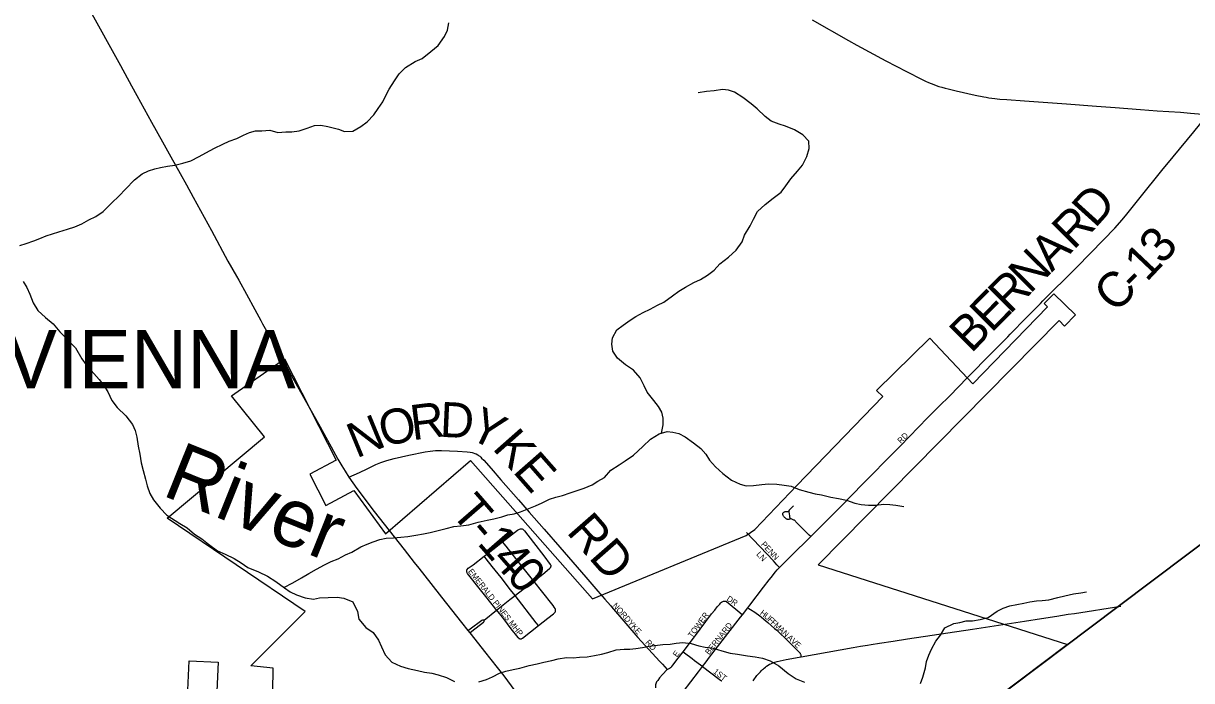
# Model space of a CAD drawing. Extents: x 1442749 to 1756758, y 235267 to 677782.
# Drawn here: x 1626273 to 1636274, y 485248 to 490876 of the extents above; entities that cross this region are included whole.
import ezdxf

# ---------------------------------------------------------------- set-up
doc = ezdxf.new("R2010")
doc.units = 0
for name, color, linetype in [('GM_X_Adjacent_County', 7, 'Continuous'), ('GM_X_City_Street', 7, 'Continuous'), ('GM_X_City_Street_Text', 7, 'Continuous'), ('GM_X_Corporation', 7, 'Continuous'), ('GM_X_Corporation_Text', 7, 'Continuous'), ('GM_X_County', 7, 'Continuous'), ('GM_X_County_Road', 7, 'Continuous'), ('GM_X_County_Road_Text', 7, 'Continuous'), ('GM_X_Major_River', 7, 'Continuous'), ('GM_X_Major_River_Text', 7, 'Continuous'), ('GM_X_Minor_River', 7, 'Continuous'), ('GM_X_State_Route', 7, 'Continuous'), ('GM_X_Township', 7, 'Continuous'), ('GM_X_Township_Road', 7, 'Continuous'), ('GM_X_Township_Road_Text', 7, 'Continuous')]:
    doc.layers.add(name, color=color, linetype=linetype)

msp = doc.modelspace()

# ---------------------------------------------------------------- linework, layer by layer
at = {"layer": 'GM_X_Adjacent_County'}
msp.add_lwpolyline([(1614700, 470050), (1618604, 472952), (1620523, 474378), (1621966, 475451), (1621997, 475474), (1628919, 480818), (1628958, 480847), (1631413, 482696), (1633248, 484078), (1633505, 484272), (1633819, 484508), (1635644, 485883), (1638042, 487688), (1640676, 489672), (1647133, 494533), (1648023, 495203), (1648788, 495779), (1655741, 500852)], dxfattribs=at)
at = {"layer": 'GM_X_City_Street'}
for points in [[(1633013, 486483), (1633279, 486749), (1633458, 486933), (1633737, 487213), (1633783, 487260), (1634014, 487497), (1634109, 487596), (1634203, 487688), (1634353, 487840)], [(1632840, 486636), (1632839, 486635), (1632837, 486634), (1632837, 486633), (1632836, 486632), (1632834, 486631), (1632833, 486631), (1632831, 486630), (1632826, 486629), (1632823, 486628), (1632819, 486628), (1632815, 486629), (1632812, 486630), (1632807, 486632), (1632803, 486634), (1632794, 486642), (1632790, 486646), (1632785, 486651), (1632782, 486654), (1632781, 486656), (1632778, 486661), (1632776, 486664), (1632775, 486668), (1632774, 486671), (1632774, 486676), (1632774, 486679), (1632775, 486682), (1632777, 486684), (1632778, 486686), (1632780, 486688), (1632780, 486689), (1632784, 486691), (1632786, 486692), (1632790, 486694), (1632794, 486695), (1632805, 486695), (1632815, 486695), (1632822, 486695), (1632828, 486694)], [(1632828, 486694), (1632828, 486697), (1632828, 486699), (1632828, 486700), (1632828, 486701), (1632828, 486702), (1632828, 486703), (1632829, 486704), (1632829, 486704), (1632830, 486706), (1632830, 486707), (1632832, 486710), (1632833, 486711), (1632834, 486713), (1632835, 486714), (1632839, 486718), (1632867, 486745)], [(1632840, 486636), (1632839, 486638), (1632838, 486640), (1632837, 486641), (1632836, 486643), (1632836, 486644), (1632835, 486646), (1632834, 486650), (1632834, 486653), (1632833, 486656), (1632833, 486660), (1632828, 486694)], [(1633013, 486483), (1633001, 486495), (1632930, 486566), (1632886, 486609), (1632883, 486613), (1632879, 486616), (1632877, 486618), (1632873, 486621), (1632870, 486623), (1632857, 486628), (1632840, 486636)], [(1630376, 486437), (1630426, 486476), (1630503, 486537), (1630519, 486546), (1630528, 486549), (1630533, 486549), (1630537, 486549), (1630543, 486547), (1630548, 486545), (1630552, 486541), (1630557, 486536), (1630562, 486530), (1630639, 486431), (1630728, 486317), (1630783, 486243), (1630786, 486239), (1630787, 486236), (1630787, 486235), (1630788, 486234), (1630788, 486232), (1630788, 486229), (1630789, 486226)], [(1632745, 486216), (1632723, 486241), (1632695, 486274), (1632464, 486518)], [(1632745, 486216), (1632751, 486223), (1632811, 486282), (1632842, 486313), (1633013, 486483)], [(1630218, 486314), (1630248, 486336), (1630291, 486371), (1630376, 486437)], [(1630644, 486099), (1630540, 486229), (1630406, 486399), (1630376, 486437)], [(1630324, 485852), (1630309, 485871), (1630076, 486166), (1630073, 486172), (1630070, 486177), (1630069, 486183), (1630069, 486190), (1630070, 486196), (1630073, 486201), (1630081, 486210), (1630123, 486241), (1630218, 486314)], [(1630482, 485977), (1630443, 486027), (1630362, 486130), (1630286, 486226), (1630236, 486290), (1630218, 486314)], [(1630644, 486099), (1630720, 486160), (1630778, 486208), (1630784, 486213), (1630787, 486217), (1630787, 486217), (1630788, 486219), (1630788, 486220), (1630788, 486222), (1630788, 486223), (1630789, 486225), (1630789, 486226)], [(1632475, 485873), (1632491, 485894), (1632608, 486048), (1632657, 486110), (1632674, 486132), (1632713, 486180), (1632727, 486197), (1632745, 486216)], [(1630482, 485977), (1630487, 485981), (1630612, 486076), (1630644, 486099)], [(1630683, 485719), (1630764, 485782), (1630812, 485821), (1630816, 485825), (1630821, 485829), (1630825, 485834), (1630827, 485839), (1630829, 485848), (1630828, 485857), (1630825, 485865), (1630818, 485876), (1630807, 485891), (1630796, 485905), (1630644, 486099)], [(1630324, 485852), (1630438, 485942), (1630482, 485977)], [(1630683, 485719), (1630663, 485744), (1630482, 485977)], [(1631192, 486014), (1631251, 485945), (1631299, 485891), (1631307, 485881), (1631414, 485757), (1631534, 485619), (1631720, 485414), (1631744, 485388), (1631784, 485343)], [(1631921, 485495), (1632010, 485611), (1632028, 485636), (1632068, 485688), (1632165, 485819), (1632191, 485852), (1632212, 485879), (1632223, 485892), (1632234, 485904), (1632240, 485911), (1632242, 485913), (1632250, 485920), (1632254, 485922), (1632262, 485927), (1632266, 485928), (1632271, 485930), (1632275, 485930), (1632280, 485930), (1632284, 485929), (1632288, 485927), (1632291, 485926), (1632293, 485925), (1632296, 485922), (1632307, 485914), (1632406, 485833), (1632430, 485813)], [(1632430, 485813), (1632475, 485873)], [(1632475, 485873), (1632484, 485867), (1632499, 485858), (1632534, 485834), (1632577, 485803), (1632592, 485791), (1632630, 485761), (1632647, 485746), (1632704, 485695), (1632722, 485679), (1632823, 485583), (1632912, 485495), (1632917, 485489), (1632920, 485486), (1632921, 485485), (1632922, 485483), (1632923, 485481), (1632924, 485478), (1632926, 485474), (1632928, 485468), (1632929, 485463), (1632930, 485459), (1632932, 485451)], [(1630219, 485767), (1630324, 485852)], [(1630324, 485852), (1630384, 485776), (1630447, 485693), (1630506, 485619), (1630511, 485614), (1630515, 485610), (1630519, 485608), (1630522, 485606), (1630527, 485605), (1630530, 485605), (1630535, 485606), (1630538, 485607), (1630540, 485609), (1630545, 485612), (1630683, 485719)], [(1632086, 485370), (1632117, 485409), (1632148, 485449), (1632305, 485652), (1632413, 485791), (1632430, 485813)], [(1630078, 485678), (1630098, 485692), (1630198, 485765), (1630201, 485767), (1630205, 485768), (1630208, 485769), (1630211, 485769), (1630214, 485768), (1630219, 485767)], [(1630094, 485657), (1630112, 485672), (1630213, 485750), (1630215, 485753), (1630218, 485756), (1630219, 485758), (1630219, 485760), (1630219, 485762), (1630219, 485767)], [(1631784, 485343), (1631807, 485356), (1631813, 485360), (1631816, 485362), (1631820, 485366), (1631824, 485370), (1631834, 485382), (1631878, 485441), (1631921, 485495)], [(1631921, 485495), (1631932, 485487), (1631999, 485438), (1632019, 485422), (1632069, 485384), (1632080, 485375), (1632086, 485370)], [(1631784, 485343), (1631744, 485302), (1631719, 485272), (1631703, 485250), (1631694, 485237), (1631690, 485229), (1631687, 485222), (1631684, 485213), (1631683, 485208), (1631683, 485204), (1631683, 485197), (1631684, 485187)], [(1631838, 485045), (1631856, 485068), (1632052, 485325), (1632086, 485370)], [(1632086, 485370), (1632230, 485261), (1632249, 485246), (1632252, 485244)]]:
    msp.add_lwpolyline(points, dxfattribs=at)
at = {"layer": 'GM_X_Corporation'}
for points in [[(1628398, 484333), (1628411, 485354), (1628219, 485374), (1628686, 485841), (1627505, 486638), (1628338, 487337), (1628054, 487687), (1628507, 488004), (1628950, 487135), (1628725, 487015), (1628861, 486748), (1629103, 486876), (1629374, 486504), (1630100, 487134), (1631145, 485950), (1632461, 486490), (1632534, 486543), (1632894, 486918), (1633630, 487680), (1633577, 487731), (1634034, 488180), (1634400, 487790), (1635040, 488449), (1635011, 488478), (1635094, 488561), (1635280, 488379), (1635185, 488282), (1635139, 488333), (1633078, 486240), (1635211, 485558), (1633823, 484511)], [(1627618, 483785), (1627691, 485418), (1627940, 485406), (1627901, 484537)]]:
    msp.add_lwpolyline(points, dxfattribs=at)
at = {"layer": 'GM_X_County'}
msp.add_lwpolyline([(1655741, 500852), (1648788, 495779), (1648023, 495203), (1647133, 494533), (1640676, 489672), (1638042, 487688), (1635644, 485883), (1633819, 484508), (1633505, 484272), (1633248, 484078), (1631413, 482696), (1628958, 480847), (1628919, 480818), (1621997, 475474), (1621966, 475451), (1620523, 474378), (1618604, 472952), (1614700, 470050)], dxfattribs=at)
at = {"layer": 'GM_X_County_Road'}
for points in [[(1635091, 488591), (1635188, 488686), (1635291, 488788), (1635521, 489022), (1635616, 489121), (1635680, 489193), (1635719, 489241), (1635833, 489385), (1636018, 489615), (1636116, 489734), (1636292, 489946), (1636417, 490099)], [(1634353, 487840), (1634564, 488055), (1634590, 488081), (1634700, 488193), (1634722, 488215), (1634860, 488356), (1634980, 488478), (1635001, 488499), (1635091, 488591)]]:
    msp.add_lwpolyline(points, dxfattribs=at)
at = {"layer": 'GM_X_Major_River'}
for points in [[(1626272, 488666), (1626303, 488615), (1626327, 488557), (1626356, 488484), (1626397, 488416), (1626462, 488357), (1626527, 488304), (1626585, 488235), (1626719, 488097), (1626774, 488004), (1626809, 487952), (1626876, 487877), (1626921, 487826), (1626963, 487775), (1626996, 487721), (1627031, 487646), (1627076, 487588), (1627151, 487515), (1627206, 487442), (1627230, 487391), (1627243, 487333), (1627256, 487257), (1627269, 487187), (1627282, 487114), (1627297, 487046), (1627318, 486974), (1627333, 486917), (1627355, 486851), (1627388, 486796), (1627445, 486724), (1627500, 486665), (1627611, 486593), (1627675, 486556), (1627738, 486503), (1627800, 486463), (1627859, 486416), (1627935, 486361), (1628000, 486330), (1628078, 486293), (1628137, 486256), (1628193, 486217), (1628286, 486180), (1628362, 486143), (1628433, 486096), (1628507, 486043), (1628558, 486010), (1628610, 485983), (1628684, 485958), (1628756, 485947), (1628808, 485957), (1628882, 485960), (1628960, 485963), (1629016, 485954), (1629092, 485923), (1629133, 485840), (1629146, 485774), (1629205, 485703), (1629266, 485660)], [(1629266, 485660), (1629313, 485594), (1629339, 485539), (1629370, 485469), (1629427, 485406), (1629501, 485373), (1629568, 485352), (1629646, 485335), (1629706, 485322), (1629770, 485311), (1629824, 485297), (1629894, 485274), (1629963, 485241)]]:
    msp.add_lwpolyline(points, dxfattribs=at)
at = {"layer": 'GM_X_Minor_River'}
for points in [[(1626242, 488974), (1626298, 488990), (1626362, 489013), (1626415, 489033), (1626469, 489056), (1626521, 489074), (1626577, 489091), (1626650, 489113), (1626712, 489134), (1626772, 489160), (1626833, 489193), (1626893, 489223), (1626956, 489266), (1627028, 489336), (1627093, 489399), (1627146, 489457), (1627223, 489536), (1627291, 489586), (1627345, 489613), (1627398, 489629), (1627448, 489643), (1627506, 489654), (1627570, 489663), (1627639, 489679), (1627705, 489700), (1627777, 489736), (1627836, 489767), (1627908, 489807), (1627979, 489840), (1628035, 489866), (1628099, 489889), (1628158, 489919), (1628210, 489942), (1628260, 489956), (1628314, 489957), (1628382, 489961), (1628450, 489942), (1628521, 489947), (1628571, 489947), (1628633, 489956), (1628701, 489978), (1628765, 490001), (1628818, 490003), (1628880, 489992), (1628970, 489969), (1629023, 489949), (1629092, 489952), (1629162, 489994), (1629215, 490033), (1629273, 490093), (1629310, 490147), (1629350, 490205), (1629375, 490258), (1629405, 490312), (1629450, 490384), (1629489, 490444), (1629543, 490499), (1629626, 490549), (1629688, 490576), (1629761, 490634), (1629824, 490687), (1629878, 490763), (1629905, 490817), (1629915, 490879)], [(1631737, 487367), (1631749, 487437), (1631750, 487496), (1631738, 487546), (1631709, 487596), (1631671, 487647), (1631614, 487719), (1631588, 487772), (1631553, 487840), (1631497, 487907), (1631428, 487953), (1631358, 488008), (1631318, 488069), (1631311, 488129), (1631317, 488183), (1631352, 488251), (1631407, 488292), (1631467, 488334), (1631517, 488365), (1631580, 488401), (1631638, 488428), (1631701, 488462), (1631755, 488490), (1631830, 488543), (1631884, 488583), (1631940, 488616), (1632013, 488656), (1632069, 488683), (1632130, 488719), (1632186, 488762), (1632235, 488816), (1632309, 488875), (1632374, 488935), (1632427, 489005), (1632447, 489062), (1632494, 489142), (1632523, 489200), (1632557, 489264), (1632624, 489325), (1632691, 489379), (1632761, 489430), (1632800, 489486), (1632842, 489544), (1632899, 489611), (1632944, 489663), (1632980, 489735), (1633001, 489805), (1632996, 489867), (1632946, 489922), (1632874, 489964), (1632798, 489995), (1632744, 490012), (1632675, 490038), (1632623, 490079), (1632555, 490144), (1632504, 490186), (1632432, 490241), (1632360, 490288), (1632308, 490304), (1632258, 490309), (1632188, 490299), (1632120, 490292), (1632050, 490282)], [(1628502, 486046), (1628580, 486085), (1628654, 486129), (1628717, 486166), (1628783, 486202), (1628852, 486241), (1628908, 486267), (1628968, 486290), (1629031, 486324), (1629085, 486349), (1629162, 486393), (1629216, 486418), (1629266, 486438), (1629324, 486457), (1629379, 486467), (1629441, 486472), (1629505, 486478), (1629563, 486483), (1629633, 486493), (1629698, 486504), (1629756, 486518), (1629892, 486552), (1629957, 486568), (1630019, 486573), (1630085, 486581), (1630167, 486604), (1630242, 486623), (1630300, 486633), (1630368, 486650), (1630420, 486668), (1630474, 486675), (1630529, 486693), (1630601, 486722), (1630657, 486744), (1630714, 486771), (1630776, 486803), (1630832, 486820), (1630889, 486834), (1630953, 486855), (1631013, 486877), (1631075, 486896), (1631142, 486926), (1631192, 486956), (1631247, 486987), (1631301, 487049), (1631372, 487096), (1631426, 487130), (1631495, 487179), (1631576, 487253), (1631642, 487316), (1631715, 487360), (1631783, 487381), (1631833, 487377), (1631885, 487364), (1631939, 487336), (1632009, 487285), (1632072, 487236), (1632114, 487186), (1632147, 487135), (1632197, 487079), (1632261, 487022), (1632336, 486965), (1632408, 486929), (1632462, 486916), (1632522, 486918), (1632594, 486927), (1632653, 486932), (1632723, 486930), (1632787, 486923), (1632847, 486913), (1632915, 486886), (1632998, 486861), (1633050, 486849), (1633106, 486838), (1633186, 486819), (1633250, 486809), (1633320, 486792), (1633392, 486767), (1633446, 486757), (1633508, 486752), (1633568, 486752), (1633639, 486759), (1633691, 486757), (1633741, 486752), (1633809, 486738)], [(1633953, 485223), (1633972, 485277), (1633995, 485359), (1634005, 485413), (1634024, 485465), (1634046, 485517), (1634085, 485587), (1634123, 485639), (1634162, 485700), (1634238, 485738), (1634291, 485747), (1634345, 485759), (1634399, 485760), (1634465, 485772), (1634533, 485789), (1634610, 485843), (1634660, 485868), (1634717, 485888), (1634777, 485901), (1634837, 485911), (1634889, 485922), (1634945, 485932), (1634996, 485935), (1635052, 485941), (1635130, 485960), (1635190, 485974), (1635263, 485991), (1635325, 486000), (1635375, 486008)], [(1630173, 485237), (1630239, 485259), (1630290, 485282), (1630350, 485312), (1630402, 485329), (1630466, 485345), (1630523, 485356), (1630603, 485378), (1630671, 485393), (1630729, 485405), (1630798, 485422), (1630850, 485434), (1630922, 485445), (1630980, 485444), (1631034, 485448), (1631099, 485453), (1631161, 485463), (1631221, 485474), (1631275, 485488), (1631349, 485511), (1631416, 485519), (1631466, 485518), (1631516, 485522), (1631572, 485531), (1631630, 485543), (1631680, 485550), (1631747, 485558), (1631811, 485561), (1631861, 485569), (1631919, 485574), (1631989, 485566), (1632055, 485547), (1632111, 485534), (1632179, 485526), (1632253, 485503), (1632323, 485484), (1632387, 485474), (1632473, 485461), (1632537, 485452), (1632599, 485440), (1632667, 485419), (1632741, 485374), (1632820, 485308), (1632888, 485263), (1632960, 485234)]]:
    msp.add_lwpolyline(points, dxfattribs=at)
at = {"layer": 'GM_X_State_Route'}
for points in [[(1626771, 491119), (1626917, 490855), (1627020, 490668), (1627103, 490515), (1627199, 490340), (1627245, 490257), (1627370, 490030), (1627463, 489860), (1627535, 489732), (1627614, 489591), (1627668, 489494), (1627726, 489388), (1627789, 489273), (1627882, 489103), (1628024, 488841), (1628097, 488710), (1628116, 488677), (1628182, 488557), (1628253, 488427), (1628305, 488333), (1628321, 488304), (1628367, 488223), (1628386, 488190), (1628418, 488132), (1628436, 488099), (1628488, 488008), (1628524, 487940), (1628565, 487865), (1628711, 487605), (1628798, 487447), (1628908, 487249), (1628966, 487145), (1629000, 487087), (1629027, 487041), (1629060, 486989), (1629127, 486892)], [(1629127, 486892), (1629277, 486696), (1629533, 486371), (1629591, 486296), (1629619, 486260), (1629657, 486210), (1629761, 486080), (1629853, 485964), (1630025, 485745), (1630078, 485678), (1630094, 485657), (1630105, 485644), (1630220, 485498), (1630328, 485361), (1630385, 485288)], [(1634399, 485690), (1634844, 485757), (1634989, 485779), (1635119, 485800), (1635218, 485816), (1635272, 485824), (1635667, 485887)], [(1633498, 485552), (1633530, 485557), (1633602, 485569), (1633720, 485587), (1633843, 485605), (1634399, 485690)], [(1632520, 485248), (1632553, 485291), (1632568, 485310), (1632582, 485325), (1632588, 485331), (1632595, 485338), (1632601, 485344), (1632608, 485350), (1632615, 485356), (1632625, 485365), (1632635, 485372), (1632650, 485381), (1632661, 485388), (1632671, 485392), (1632690, 485400), (1632706, 485406), (1632727, 485412), (1632751, 485418), (1632802, 485428), (1632915, 485448), (1632932, 485451), (1633377, 485531), (1633440, 485542), (1633498, 485552)], [(1630385, 485288), (1630450, 485204), (1630463, 485185), (1630483, 485157), (1630495, 485140), (1630508, 485118), (1630518, 485100), (1630532, 485070), (1630541, 485045), (1630550, 485010), (1630572, 484897), (1630572, 484894), (1630588, 484790), (1630603, 484673), (1630612, 484607), (1630615, 484582), (1630624, 484521), (1630628, 484498), (1630636, 484462), (1630640, 484445), (1630647, 484423), (1630652, 484405)]]:
    msp.add_lwpolyline(points, dxfattribs=at)
at = {"layer": 'GM_X_Township'}
msp.add_lwpolyline([(1642919, 502379), (1644427, 500259), (1647406, 496053), (1648023, 495203), (1647133, 494533), (1640676, 489672), (1638042, 487688), (1635644, 485883), (1633819, 484508), (1633505, 484272), (1633248, 484078), (1631413, 482696), (1628958, 480847), (1628919, 480818), (1621997, 475474), (1621966, 475451), (1620523, 474378), (1618604, 472952), (1618173, 474474), (1617335, 477441), (1616958, 478774)], dxfattribs=at)
at = {"layer": 'GM_X_Township_Road'}
for points in [[(1633025, 490907), (1633338, 490728), (1633407, 490689), (1633655, 490556), (1633833, 490463), (1633967, 490395), (1633995, 490381), (1634021, 490369), (1634044, 490360), (1634066, 490351), (1634086, 490344), (1634110, 490336), (1634136, 490329), (1634163, 490321), (1634191, 490314), (1634259, 490298), (1634422, 490261), (1634495, 490247), (1634516, 490243), (1634539, 490239), (1634564, 490235), (1634590, 490231), (1634610, 490229), (1634632, 490227), (1634691, 490223), (1634842, 490213), (1635202, 490187), (1635460, 490168), (1635620, 490154), (1635836, 490137), (1635980, 490127), (1636180, 490115), (1636265, 490108), (1636366, 490099)], [(1629060, 486989), (1629149, 487030), (1629217, 487063), (1629291, 487098), (1629333, 487115), (1629383, 487133), (1629446, 487150), (1629574, 487179), (1629712, 487207), (1629754, 487214), (1629800, 487218), (1629853, 487218), (1629990, 487213), (1630072, 487208), (1630098, 487205), (1630114, 487201), (1630124, 487198), (1630138, 487193), (1630148, 487189), (1630162, 487181), (1630170, 487176), (1630180, 487169), (1630188, 487162), (1630196, 487154), (1630214, 487136), (1630277, 487065), (1630361, 486968), (1630512, 486795), (1630603, 486692), (1630730, 486545), (1630866, 486390), (1631088, 486135), (1631192, 486014)]]:
    msp.add_lwpolyline(points, dxfattribs=at)

# ---------------------------------------------------------------- texts
at = {"layer": 'GM_X_City_Street_Text'}
for s, rotation, p in [('RD', 45, (1633785, 487274)), ('PENN', 312.7943, (1632584, 486412)), ('LN', 312.8801, (1632544, 486327)), ('EMERALD PINES MHP', 308.2223, (1630077, 486182)), ('DR', 325.4938, (1632288, 485938)), ('NORDYKE', 311.4232, (1631313, 485888)), ('TOWER', 53.9013, (1631998, 485610)), ('H', 321.7396, (1632574, 485819)), ('U', 320.4799, (1632609, 485792)), ('F', 317.5315, (1632642, 485764)), ('F', 316.9709, (1632668, 485740)), ('BERNARD', 51.6089, (1632143, 485465)), ('M', 316.9323, (1632694, 485716)), ('A', 316.96, (1632732, 485680)), ('N', 316.9323, (1632765, 485650)), ('RD', 312.8801, (1631594, 485571)), ('A', 316.9323, (1632806, 485611)), ('V', 316.96, (1632839, 485581)), ('E', 316.9323, (1632871, 485551)), ('E', 53.464, (1631868, 485445)), ('1ST', 322.1275, (1632174, 485317))]:
    msp.add_text(s, height=50, rotation=rotation, dxfattribs=at).set_placement(p)
at = {"layer": 'GM_X_Corporation_Text'}
msp.add_text('NEW VIENNA', height=500, rotation=0, dxfattribs=at).set_placement((1624369, 487751))
at = {"layer": 'GM_X_County_Road_Text'}
for s, rotation, p in [('D', 47.9278, (1635447, 489115)), ('R', 45.3903, (1635264, 488929)), ('3', 49.5163, (1636026, 488802)), ('A', 45.2218, (1635077, 488741)), ('N', 45.2189, (1634891, 488554)), ('1', 46.6082, (1635888, 488655)), ('R', 45.2208, (1634718, 488379)), ('C', 45.0469, (1635621, 488386)), ('-', 45.4355, (1635797, 488562)), ('E', 45.2239, (1634560, 488220)), ('B', 45.218, (1634386, 488045))]:
    msp.add_text(s, height=300, rotation=rotation, dxfattribs=at).set_placement(p)
at = {"layer": 'GM_X_Major_River_Text'}
msp.add_text('River', height=500, rotation=338.1059, dxfattribs=at).set_placement((1627448, 486839))
at = {"layer": 'GM_X_Township_Road_Text'}
for s, rotation, p in [('O', 13.5715, (1629356, 487246)), ('R', 7.1023, (1629604, 487306)), ('D', 357.3726, (1629835, 487336)), ('Y', 334.1453, (1630068, 487332)), ('N', 22.4055, (1629124, 487149)), ('K', 311.4611, (1630281, 487236)), ('E', 311.2791, (1630455, 487038)), ('T', 310.9602, (1629923, 486684)), ('RD', 311.1858, (1630915, 486518)), ('-', 310.9848, (1630070, 486515)), ('1', 311.0199, (1630151, 486422)), ('4', 311.2012, (1630273, 486281)), ('0', 311.8431, (1630397, 486140))]:
    msp.add_text(s, height=300, rotation=rotation, dxfattribs=at).set_placement(p)

doc.saveas('drawing.dxf')
